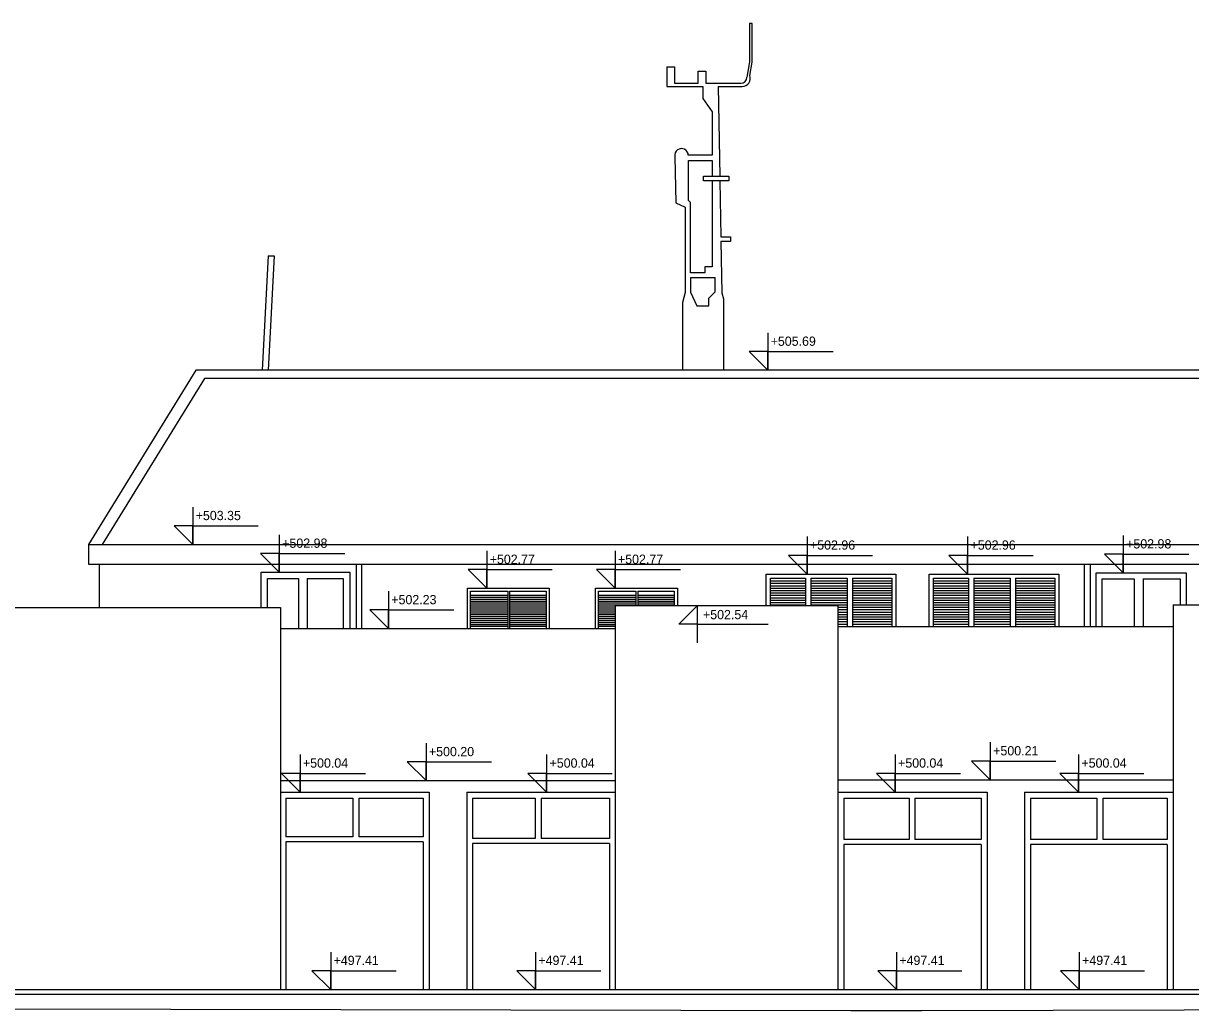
# Model space of a CAD drawing. Extents: x 224 to 311.2, y 493.1 to 511.4.
# Drawn here: x 264.21 to 279.82, y 497.12 to 510.32 of the extents above; entities that cross this region are included whole.
import ezdxf

# ---------------------------------------------------------------- set-up
doc = ezdxf.new("R2010")
doc.units = 0
for name, color, linetype in [('antena', 7, 'Continuous'), ('okap', 7, 'Continuous'), ('okna', 7, 'Continuous'), ('strecha_sikma', 7, 'Continuous'), ('teren', 7, 'Continuous'), ('vyustky_vzduchotechniky', 7, 'Continuous'), ('zakl_tenka', 7, 'Continuous'), ('znaceni', 7, 'Continuous')]:
    doc.layers.add(name, color=color, linetype=linetype)

msp = doc.modelspace()

# ---------------------------------------------------------------- linework, layer by layer
at = {"layer": 'antena'}
for p, q in [((273.952, 510.323), (273.917, 510.323)), ((273.917, 510.323), (273.917, 509.808)), ((273.952, 509.803), (273.952, 510.323)), ((272.812, 509.743), (272.912, 509.743)), ((272.812, 509.743), (272.812, 509.478)), ((272.912, 509.743), (272.912, 509.523)), ((273.917, 509.808), (273.881, 509.605)), ((273.921, 509.626), (273.952, 509.803)), ((273.232, 509.523), (273.232, 509.683)), ((273.232, 509.683), (273.332, 509.683)), ((273.332, 509.683), (273.332, 509.523)), ((272.812, 509.478), (273.292, 509.478)), ((272.912, 509.523), (273.232, 509.523)), ((273.292, 509.478), (273.292, 509.318)), ((273.332, 509.523), (273.799, 509.523)), ((273.498, 509.478), (273.519, 508.279)), ((273.498, 509.478), (273.818, 509.478)), ((273.292, 509.318), (273.418, 509.138)), ((273.418, 509.138), (273.418, 508.558)), ((272.92, 508.544), (272.93, 507.924)), ((273.418, 508.558), (273.098, 508.558)), ((273.099, 508.487), (273.418, 508.487)), ((273.099, 507.955), (273.099, 508.487)), ((273.418, 508.487), (273.418, 508.279)), ((273.301, 508.279), (273.641, 508.279)), ((273.301, 508.219), (273.301, 508.279)), ((273.641, 508.219), (273.301, 508.219)), ((273.418, 508.219), (273.418, 507.067)), ((273.52, 508.219), (273.533, 507.47)), ((273.641, 508.279), (273.641, 508.219)), ((272.93, 507.924), (273.057, 507.865)), ((273.057, 507.865), (273.057, 507.685)), ((273.127, 507.927), (273.099, 507.955)), ((273.127, 506.987), (273.127, 507.927)), ((273.057, 507.685), (273.057, 506.725)), ((273.533, 507.47), (273.663, 507.47)), ((273.663, 507.405), (273.535, 507.405)), ((273.535, 507.405), (273.547, 506.719)), ((273.663, 507.47), (273.663, 507.405)), ((267.481, 507.213), (267.401, 505.686)), ((267.481, 507.213), (267.561, 507.213)), ((267.561, 507.213), (267.481, 505.686)), ((273.418, 507.067), (273.318, 507.067)), ((273.318, 507.067), (273.318, 506.987)), ((273.318, 506.987), (273.127, 506.987)), ((273.127, 506.926), (273.127, 506.727)), ((273.127, 506.926), (273.457, 506.926)), ((273.457, 506.731), (273.457, 506.926)), ((273.057, 506.725), (273.021, 506.59)), ((273.127, 506.727), (273.212, 506.546)), ((273.372, 506.646), (273.457, 506.731)), ((273.021, 506.59), (273.021, 505.686)), ((273.372, 506.546), (273.372, 506.646)), ((273.547, 506.719), (273.567, 506.641)), ((273.567, 506.641), (273.567, 505.686)), ((273.212, 506.546), (273.372, 506.546))]:
    msp.add_line(p, q, dxfattribs=at)
for centre, radius, start, end in [((273.799, 509.605), 0.0823, 270, 0), ((273.818, 509.588), 0.11, 270, 20), ((273.008, 508.558), 0.09, 0, 188.9783)]:
    msp.add_arc(centre, radius, start, end, dxfattribs=at)
at = {"layer": 'okap'}
for p, q in [((265.078, 503.354), (265.078, 503.091)), ((265.078, 503.091), (282.012, 503.091)), ((268.657, 503.091), (268.657, 502.229)), ((268.728, 503.091), (268.728, 502.229)), ((278.393, 503.091), (278.393, 502.258)), ((278.471, 503.091), (278.471, 502.258))]:
    msp.add_line(p, q, dxfattribs=at)
at = {"layer": 'okna'}
for p, q in [((267.885, 502.899), (267.885, 502.229)), ((268, 502.899), (268, 502.229)), ((279.061, 502.895), (279.061, 502.258)), ((279.181, 502.895), (279.181, 502.258)), ((267.718, 499.964), (267.718, 499.443)), ((267.718, 499.964), (268.611, 499.964)), ((268.611, 499.964), (268.611, 499.443)), ((268.691, 499.964), (268.691, 499.443)), ((268.691, 499.964), (269.555, 499.964)), ((269.555, 499.964), (269.555, 499.443)), ((270.214, 499.964), (270.214, 499.423)), ((270.214, 499.964), (271.052, 499.964)), ((271.052, 499.964), (271.052, 499.423)), ((271.132, 499.964), (271.132, 499.423)), ((271.132, 499.964), (272.043, 499.964)), ((272.043, 499.964), (272.043, 499.423)), ((275.178, 499.964), (275.178, 499.409)), ((275.178, 499.964), (276.05, 499.964)), ((276.05, 499.964), (276.05, 499.409)), ((276.13, 499.964), (276.13, 499.409)), ((276.13, 499.964), (277.015, 499.964)), ((277.015, 499.964), (277.015, 499.409)), ((277.674, 499.964), (277.674, 499.409)), ((277.674, 499.964), (278.561, 499.964)), ((278.561, 499.964), (278.561, 499.409)), ((278.641, 499.964), (278.641, 499.409)), ((278.641, 499.964), (279.503, 499.964)), ((279.503, 499.964), (279.503, 499.409)), ((268.611, 499.443), (267.718, 499.443)), ((269.555, 499.443), (268.691, 499.443)), ((271.052, 499.423), (270.214, 499.423)), ((272.043, 499.423), (271.132, 499.423)), ((276.05, 499.409), (275.178, 499.409)), ((277.015, 499.409), (276.13, 499.409)), ((278.561, 499.409), (277.674, 499.409)), ((279.503, 499.409), (278.641, 499.409)), ((269.555, 499.376), (267.718, 499.376)), ((267.718, 499.376), (267.718, 497.405)), ((269.555, 499.376), (269.555, 497.405)), ((272.043, 499.356), (270.214, 499.356)), ((270.214, 499.356), (270.214, 497.405)), ((272.043, 499.356), (272.043, 497.405)), ((277.015, 499.342), (275.178, 499.342)), ((275.178, 499.342), (275.178, 497.405)), ((277.015, 499.342), (277.015, 497.405)), ((279.503, 499.342), (277.674, 499.342)), ((277.674, 499.342), (277.674, 497.405)), ((279.503, 499.342), (279.503, 497.405))]:
    msp.add_line(p, q, dxfattribs=at)
for points in [[(267.472, 502.511), (267.472, 502.899), (267.885, 502.899)], [(268, 502.899), (268.485, 502.899), (268.485, 502.229)], [(278.634, 502.258), (278.634, 502.895), (279.061, 502.895)], [(279.181, 502.895), (279.676, 502.895), (279.676, 502.546)]]:
    msp.add_lwpolyline(points, dxfattribs=at)
at = {"layer": 'strecha_sikma'}
for p, q in [((266.513, 505.686), (265.078, 503.354)), ((280.531, 505.686), (266.513, 505.686)), ((266.629, 505.576), (265.262, 503.354)), ((280.451, 505.576), (266.629, 505.576)), ((265.078, 503.354), (282.012, 503.354)), ((267.643, 502.229), (272.119, 502.229)), ((275.098, 502.258), (279.583, 502.258)), ((267.643, 500.197), (272.119, 500.197)), ((275.098, 500.209), (279.583, 500.209))]:
    msp.add_line(p, q, dxfattribs=at)
at = {"layer": 'teren'}
msp.add_lwpolyline([(260.099, 497.175), (263.904, 497.145), (275.27, 497.123), (276.223, 497.121), (292.012, 497.161), (304.698, 497.168)], dxfattribs=at)
at = {"layer": 'vyustky_vzduchotechniky'}
for p, q in [((274.197, 502.867), (274.668, 502.867)), ((274.197, 502.835), (274.668, 502.835)), ((274.668, 502.902), (274.668, 502.539)), ((274.737, 502.902), (274.737, 502.539)), ((274.737, 502.867), (275.225, 502.867)), ((274.737, 502.835), (275.225, 502.835)), ((275.225, 502.902), (275.225, 502.258)), ((275.295, 502.902), (275.295, 502.258)), ((275.295, 502.902), (275.819, 502.902)), ((275.295, 502.867), (275.819, 502.867)), ((275.295, 502.835), (275.819, 502.835)), ((276.376, 502.867), (276.847, 502.867)), ((276.376, 502.835), (276.847, 502.835)), ((276.847, 502.902), (276.847, 502.258)), ((276.915, 502.902), (276.915, 502.258)), ((276.915, 502.867), (277.403, 502.867)), ((276.915, 502.835), (277.403, 502.835)), ((277.403, 502.902), (277.403, 502.258)), ((277.473, 502.902), (277.473, 502.258)), ((277.473, 502.902), (277.998, 502.902)), ((277.473, 502.867), (277.998, 502.867)), ((277.473, 502.835), (277.998, 502.835)), ((270.186, 502.676), (270.686, 502.676)), ((270.686, 502.728), (270.686, 502.229)), ((270.709, 502.728), (270.709, 502.229)), ((270.709, 502.676), (271.198, 502.676)), ((271.899, 502.676), (272.399, 502.676)), ((272.399, 502.728), (272.399, 502.539)), ((272.423, 502.728), (272.423, 502.539)), ((272.423, 502.676), (272.911, 502.676)), ((274.197, 502.803), (274.668, 502.803)), ((274.197, 502.771), (274.668, 502.771)), ((274.197, 502.739), (274.668, 502.739)), ((274.197, 502.707), (274.668, 502.707)), ((274.197, 502.675), (274.668, 502.675)), ((274.737, 502.803), (275.225, 502.803)), ((274.737, 502.771), (275.225, 502.771)), ((274.737, 502.739), (275.225, 502.739)), ((274.737, 502.707), (275.225, 502.707)), ((274.737, 502.675), (275.225, 502.675)), ((275.295, 502.803), (275.819, 502.803)), ((275.295, 502.771), (275.819, 502.771)), ((275.295, 502.739), (275.819, 502.739)), ((275.295, 502.707), (275.819, 502.707)), ((275.295, 502.675), (275.819, 502.675)), ((276.376, 502.803), (276.847, 502.803)), ((276.376, 502.771), (276.847, 502.771)), ((276.376, 502.739), (276.847, 502.739)), ((276.376, 502.707), (276.847, 502.707)), ((276.376, 502.675), (276.847, 502.675)), ((276.915, 502.803), (277.403, 502.803)), ((276.915, 502.771), (277.403, 502.771)), ((276.915, 502.739), (277.403, 502.739)), ((276.915, 502.707), (277.403, 502.707)), ((276.915, 502.675), (277.403, 502.675)), ((277.473, 502.803), (277.998, 502.803)), ((277.473, 502.771), (277.998, 502.771)), ((277.473, 502.739), (277.998, 502.739)), ((277.473, 502.707), (277.998, 502.707)), ((277.473, 502.675), (277.998, 502.675)), ((270.186, 502.65), (270.686, 502.65)), ((270.186, 502.624), (270.686, 502.624)), ((270.186, 502.598), (270.686, 502.598)), ((270.186, 502.572), (270.686, 502.572)), ((270.186, 502.546), (270.686, 502.546)), ((270.186, 502.52), (270.686, 502.52)), ((270.709, 502.65), (271.198, 502.65)), ((270.709, 502.624), (271.198, 502.624)), ((270.709, 502.598), (271.198, 502.598)), ((270.709, 502.572), (271.198, 502.572)), ((270.709, 502.546), (271.198, 502.546)), ((270.709, 502.52), (271.198, 502.52)), ((271.899, 502.65), (272.399, 502.65)), ((271.899, 502.624), (272.399, 502.624)), ((271.899, 502.598), (272.399, 502.598)), ((271.899, 502.572), (272.399, 502.572)), ((271.899, 502.546), (272.399, 502.546)), ((271.899, 502.52), (272.119, 502.52)), ((272.423, 502.65), (272.911, 502.65)), ((272.423, 502.624), (272.911, 502.624)), ((272.423, 502.598), (272.911, 502.598)), ((272.423, 502.572), (272.911, 502.572)), ((272.423, 502.546), (272.911, 502.546)), ((274.197, 502.643), (274.668, 502.643)), ((274.197, 502.611), (274.668, 502.611)), ((274.197, 502.579), (274.668, 502.579)), ((274.197, 502.547), (274.668, 502.547)), ((274.737, 502.643), (275.225, 502.643)), ((274.737, 502.611), (275.225, 502.611)), ((274.737, 502.579), (275.225, 502.579)), ((274.737, 502.547), (275.225, 502.547)), ((275.098, 502.515), (275.225, 502.515)), ((275.295, 502.643), (275.819, 502.643)), ((275.295, 502.611), (275.819, 502.611)), ((275.295, 502.579), (275.819, 502.579)), ((275.295, 502.547), (275.819, 502.547)), ((275.295, 502.515), (275.819, 502.515)), ((276.376, 502.643), (276.847, 502.643)), ((276.376, 502.611), (276.847, 502.611)), ((276.376, 502.579), (276.847, 502.579)), ((276.376, 502.547), (276.847, 502.547)), ((276.376, 502.515), (276.847, 502.515)), ((276.915, 502.643), (277.403, 502.643)), ((276.915, 502.611), (277.403, 502.611)), ((276.915, 502.579), (277.403, 502.579)), ((276.915, 502.547), (277.403, 502.547)), ((276.915, 502.515), (277.403, 502.515)), ((277.473, 502.643), (277.998, 502.643)), ((277.473, 502.611), (277.998, 502.611)), ((277.473, 502.579), (277.998, 502.579)), ((277.473, 502.547), (277.998, 502.547)), ((277.473, 502.515), (277.998, 502.515)), ((270.186, 502.494), (270.686, 502.494)), ((270.186, 502.468), (270.686, 502.468)), ((270.186, 502.442), (270.686, 502.442)), ((270.186, 502.416), (270.686, 502.416)), ((270.186, 502.39), (270.686, 502.39)), ((270.186, 502.364), (270.686, 502.364)), ((270.709, 502.494), (271.198, 502.494)), ((270.709, 502.468), (271.198, 502.468)), ((270.709, 502.442), (271.198, 502.442)), ((270.709, 502.416), (271.198, 502.416)), ((270.709, 502.39), (271.198, 502.39)), ((270.709, 502.364), (271.198, 502.364)), ((271.899, 502.494), (272.119, 502.494)), ((271.899, 502.468), (272.119, 502.468)), ((271.899, 502.442), (272.119, 502.442)), ((271.899, 502.416), (272.119, 502.416)), ((271.899, 502.39), (272.119, 502.39)), ((271.899, 502.364), (272.119, 502.364)), ((275.098, 502.483), (275.225, 502.483)), ((275.098, 502.451), (275.225, 502.451)), ((275.098, 502.419), (275.225, 502.419)), ((275.098, 502.387), (275.225, 502.387)), ((275.098, 502.355), (275.225, 502.355)), ((275.295, 502.483), (275.819, 502.483)), ((275.295, 502.451), (275.819, 502.451)), ((275.295, 502.419), (275.819, 502.419)), ((275.295, 502.387), (275.819, 502.387)), ((275.295, 502.355), (275.819, 502.355)), ((276.376, 502.483), (276.847, 502.483)), ((276.376, 502.451), (276.847, 502.451)), ((276.376, 502.419), (276.847, 502.419)), ((276.376, 502.387), (276.847, 502.387)), ((276.376, 502.355), (276.847, 502.355)), ((276.915, 502.483), (277.403, 502.483)), ((276.915, 502.451), (277.403, 502.451)), ((276.915, 502.419), (277.403, 502.419)), ((276.915, 502.387), (277.403, 502.387)), ((276.915, 502.355), (277.403, 502.355)), ((277.473, 502.483), (277.998, 502.483)), ((277.473, 502.451), (277.998, 502.451)), ((277.473, 502.419), (277.998, 502.419)), ((277.473, 502.387), (277.998, 502.387)), ((277.473, 502.355), (277.998, 502.355)), ((270.186, 502.338), (270.686, 502.338)), ((270.186, 502.312), (270.686, 502.312)), ((270.186, 502.286), (270.686, 502.286)), ((270.186, 502.26), (270.686, 502.26)), ((270.709, 502.338), (271.198, 502.338)), ((270.709, 502.312), (271.198, 502.312)), ((270.709, 502.286), (271.198, 502.286)), ((270.709, 502.26), (271.198, 502.26)), ((271.899, 502.338), (272.119, 502.338)), ((271.899, 502.312), (272.119, 502.312)), ((271.899, 502.286), (272.119, 502.286)), ((271.899, 502.26), (272.119, 502.26)), ((275.098, 502.323), (275.225, 502.323)), ((275.098, 502.291), (275.225, 502.291)), ((275.295, 502.323), (275.819, 502.323)), ((275.295, 502.291), (275.819, 502.291)), ((276.376, 502.323), (276.847, 502.323)), ((276.376, 502.291), (276.847, 502.291)), ((276.915, 502.323), (277.403, 502.323)), ((276.915, 502.291), (277.403, 502.291)), ((277.473, 502.323), (277.998, 502.323)), ((277.473, 502.291), (277.998, 502.291))]:
    msp.add_line(p, q, dxfattribs=at)
for points in [[(274.14, 502.539), (274.14, 502.959), (275.876, 502.959), (275.876, 502.258)], [(274.197, 502.539), (274.197, 502.902), (274.668, 502.902)], [(274.737, 502.902), (275.225, 502.902)], [(275.819, 502.902), (275.819, 502.258)], [(276.319, 502.258), (276.319, 502.959), (278.055, 502.959), (278.055, 502.258)], [(276.376, 502.258), (276.376, 502.902), (276.847, 502.902)], [(276.915, 502.902), (277.403, 502.902)], [(277.998, 502.902), (277.998, 502.258)], [(270.144, 502.229), (270.144, 502.769), (271.24, 502.769), (271.24, 502.229)], [(270.186, 502.229), (270.186, 502.728), (270.686, 502.728)], [(270.709, 502.728), (271.198, 502.728), (271.198, 502.229)], [(271.857, 502.229), (271.857, 502.769), (272.953, 502.769), (272.953, 502.539)], [(271.899, 502.229), (271.899, 502.728), (272.399, 502.728)], [(272.423, 502.728), (272.911, 502.728), (272.911, 502.539)]]:
    msp.add_lwpolyline(points, dxfattribs=at)
at = {"layer": 'zakl_tenka'}
for p, q in [((265.221, 503.091), (265.221, 502.511)), ((255.862, 502.511), (267.643, 502.511)), ((267.643, 502.511), (267.643, 497.405)), ((272.119, 502.539), (272.119, 497.405)), ((272.119, 502.539), (275.098, 502.539)), ((275.098, 502.539), (275.098, 497.405)), ((279.583, 502.546), (279.583, 497.405)), ((279.583, 502.546), (311.105, 502.546)), ((267.643, 500.044), (269.632, 500.044)), ((269.632, 500.044), (269.632, 497.405)), ((270.138, 500.044), (272.119, 500.044)), ((270.138, 500.044), (270.138, 497.405)), ((275.098, 500.044), (277.095, 500.044)), ((277.095, 500.044), (277.095, 497.405)), ((277.594, 500.044), (279.583, 500.044)), ((277.594, 500.044), (277.594, 497.405)), ((260.099, 497.405), (289.987, 497.405)), ((260.099, 497.339), (289.987, 497.339))]:
    msp.add_line(p, q, dxfattribs=at)
for points in [[(267.387, 502.511), (267.387, 502.985), (268.57, 502.985), (268.57, 502.229)], [(278.554, 502.258), (278.554, 502.975), (279.756, 502.975), (279.756, 502.546)]]:
    msp.add_lwpolyline(points, dxfattribs=at)
at = {"layer": 'znaceni'}
for p, q in [((274.161, 506.186), (274.161, 505.686)), ((274.161, 505.936), (273.911, 505.936)), ((273.911, 505.936), (274.161, 505.686)), ((274.161, 505.686), (274.161, 505.936)), ((274.161, 505.936), (275.036, 505.936)), ((266.472, 503.854), (266.472, 503.354)), ((266.472, 503.604), (266.222, 503.604)), ((266.222, 503.604), (266.472, 503.354)), ((266.472, 503.354), (266.472, 503.604)), ((266.472, 503.604), (267.347, 503.604)), ((267.629, 503.485), (267.629, 502.985)), ((274.687, 503.459), (274.687, 502.959)), ((276.834, 503.459), (276.834, 502.959)), ((278.915, 503.475), (278.915, 502.975)), ((267.629, 503.235), (267.379, 503.235)), ((267.379, 503.235), (267.629, 502.985)), ((267.629, 502.985), (267.629, 503.235)), ((267.629, 503.235), (268.504, 503.235)), ((270.404, 503.269), (270.404, 502.769)), ((272.119, 503.269), (272.119, 502.769)), ((274.687, 503.209), (274.437, 503.209)), ((274.437, 503.209), (274.687, 502.959)), ((274.687, 502.959), (274.687, 503.209)), ((274.687, 503.209), (275.562, 503.209)), ((276.834, 503.209), (276.584, 503.209)), ((276.584, 503.209), (276.834, 502.959)), ((276.834, 502.959), (276.834, 503.209)), ((276.834, 503.209), (277.709, 503.209)), ((278.915, 503.225), (278.665, 503.225)), ((278.665, 503.225), (278.915, 502.975)), ((278.915, 502.975), (278.915, 503.225)), ((278.915, 503.225), (279.79, 503.225)), ((270.404, 503.019), (270.154, 503.019)), ((270.154, 503.019), (270.404, 502.769)), ((270.404, 502.769), (270.404, 503.019)), ((270.404, 503.019), (271.279, 503.019)), ((272.119, 503.019), (271.869, 503.019)), ((271.869, 503.019), (272.119, 502.769)), ((272.119, 502.769), (272.119, 503.019)), ((272.119, 503.019), (272.994, 503.019)), ((269.088, 502.729), (269.088, 502.229)), ((272.972, 502.289), (273.222, 502.539)), ((273.222, 502.039), (273.222, 502.539)), ((269.088, 502.479), (268.838, 502.479)), ((268.838, 502.479), (269.088, 502.229)), ((269.088, 502.229), (269.088, 502.479)), ((269.088, 502.479), (269.963, 502.479)), ((273.222, 502.289), (272.972, 502.289)), ((273.222, 502.289), (274.168, 502.289)), ((269.591, 500.697), (269.591, 500.197)), ((277.137, 500.709), (277.137, 500.209)), ((267.907, 500.544), (267.907, 500.044)), ((271.204, 500.544), (271.204, 500.044)), ((275.866, 500.544), (275.866, 500.044)), ((278.318, 500.544), (278.318, 500.044)), ((269.591, 500.447), (269.341, 500.447)), ((269.341, 500.447), (269.591, 500.197)), ((269.591, 500.197), (269.591, 500.447)), ((269.591, 500.447), (270.466, 500.447)), ((277.137, 500.459), (276.887, 500.459)), ((276.887, 500.459), (277.137, 500.209)), ((277.137, 500.209), (277.137, 500.459)), ((277.137, 500.459), (278.012, 500.459)), ((267.907, 500.294), (267.657, 500.294)), ((267.657, 500.294), (267.907, 500.044)), ((267.907, 500.044), (267.907, 500.294)), ((267.907, 500.294), (268.782, 500.294)), ((271.204, 500.294), (270.954, 500.294)), ((270.954, 500.294), (271.204, 500.044)), ((271.204, 500.044), (271.204, 500.294)), ((271.204, 500.294), (272.079, 500.294)), ((275.866, 500.294), (275.616, 500.294)), ((275.616, 500.294), (275.866, 500.044)), ((275.866, 500.044), (275.866, 500.294)), ((275.866, 500.294), (276.74, 500.294)), ((278.318, 500.294), (278.068, 500.294)), ((278.068, 500.294), (278.318, 500.044)), ((278.318, 500.044), (278.318, 500.294)), ((278.318, 500.294), (279.192, 500.294)), ((268.316, 497.905), (268.316, 497.405)), ((271.055, 497.905), (271.055, 497.405)), ((275.882, 497.905), (275.882, 497.405)), ((278.326, 497.905), (278.326, 497.405)), ((268.316, 497.655), (268.066, 497.655)), ((268.066, 497.655), (268.316, 497.405)), ((268.316, 497.405), (268.316, 497.655)), ((268.316, 497.655), (269.191, 497.655)), ((271.055, 497.655), (270.805, 497.655)), ((270.805, 497.655), (271.055, 497.405)), ((271.055, 497.405), (271.055, 497.655)), ((271.055, 497.655), (271.93, 497.655)), ((275.882, 497.655), (275.632, 497.655)), ((275.632, 497.655), (275.882, 497.405)), ((275.882, 497.405), (275.882, 497.655)), ((275.882, 497.655), (276.757, 497.655)), ((278.326, 497.655), (278.076, 497.655)), ((278.076, 497.655), (278.326, 497.405)), ((278.326, 497.405), (278.326, 497.655)), ((278.326, 497.655), (279.201, 497.655))]:
    msp.add_line(p, q, dxfattribs=at)

# ---------------------------------------------------------------- texts
for s, p in [('+505.69', (274.2, 506.011)), ('+503.35', (266.511, 503.68)), ('+502.98', (267.668, 503.31)), ('+502.96', (274.726, 503.285)), ('+502.96', (276.873, 503.285)), ('+502.98', (278.954, 503.301)), ('+502.77', (270.443, 503.095)), ('+502.77', (272.158, 503.095)), ('+502.23', (269.127, 502.555)), ('+502.54', (273.295, 502.355)), ('+500.20', (269.63, 500.523)), ('+500.21', (277.176, 500.534)), ('+500.04', (267.945, 500.37)), ('+500.04', (271.243, 500.37)), ('+500.04', (275.904, 500.37)), ('+500.04', (278.356, 500.37)), ('+497.41', (268.355, 497.731)), ('+497.41', (271.094, 497.731)), ('+497.41', (275.921, 497.731)), ('+497.41', (278.365, 497.731))]:
    msp.add_text(s, height=0.124, dxfattribs=at).set_placement(p)

doc.saveas('drawing.dxf')
